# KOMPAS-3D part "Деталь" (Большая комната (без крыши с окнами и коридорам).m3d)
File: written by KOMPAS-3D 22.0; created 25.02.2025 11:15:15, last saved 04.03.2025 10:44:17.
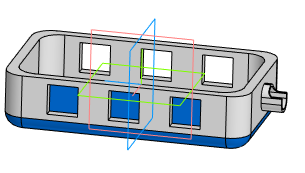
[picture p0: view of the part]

Document properties: Автор: Пользователь Windows; Полное имя файла: C:\Users\Student\Documents\Картошечка\База Сабнатика\Большая комната\Большая комната (без крыши с окнами и коридорам).m3d

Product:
- Part/product: Деталь
    Масса: 0.674503

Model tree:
1. Эскиз:1
2. Элемент выдавливания:1
     Расстояние 1 = 35
3. Скругление:2  (with: Элемент выдавливания:1)
     Радиус = 10
4. Скругление:1  (with: Элемент выдавливания:1)
     Радиус = 7
5. Эскиз:3  (with: Элемент выдавливания:1)
6. Элемент выдавливания:2
     Расстояние 2 = 7
7. Эскиз:4  (with: Элемент выдавливания:2)
8. Элемент выдавливания:3
     Расстояние 2 = 21
9. Эскиз:5  (with: Элемент выдавливания:1, Элемент выдавливания:2)
10. Элемент выдавливания:4
     Расстояние 2 = 70
11. Эскиз:6  (with: Элемент выдавливания:1)
12. Элемент выдавливания:5
     Расстояние 1 = 10
13. Эскиз:7  (with: Элемент выдавливания:5)
14. Элемент выдавливания:6
     Расстояние 2 = 5
15. Скругление:3  (with: Элемент выдавливания:6)
     Радиус = 3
